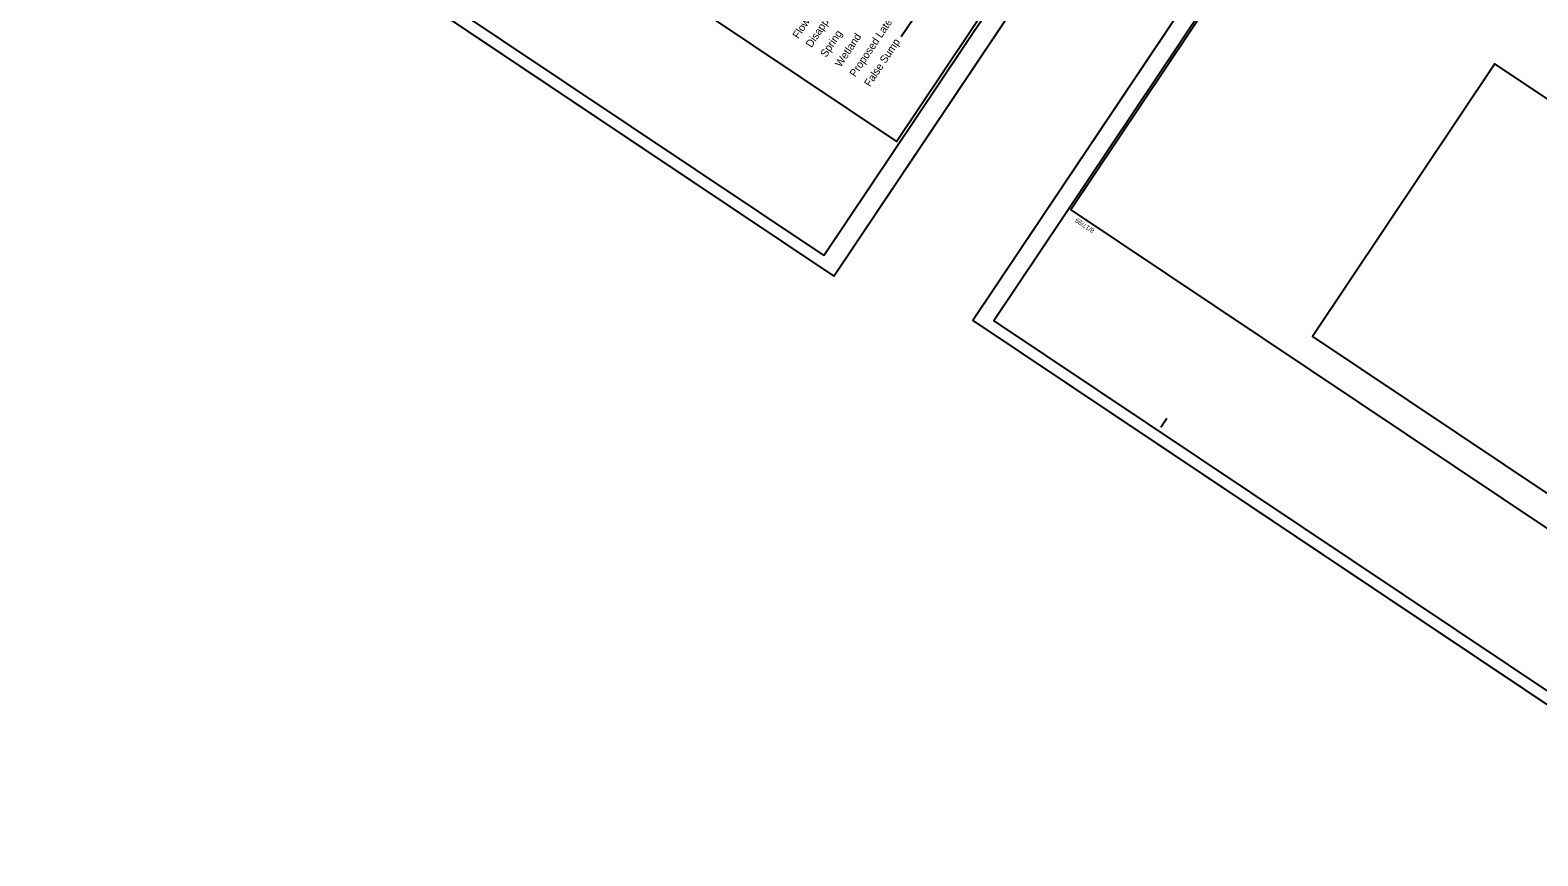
# Model space of a CAD drawing. Extents: x 1715610 to 1720914, y 798298 to 802505.
# Drawn here: x 1717996 to 1719710, y 798298 to 799237 of the extents above; entities that cross this region are included whole.
import ezdxf

# ---------------------------------------------------------------- set-up
doc = ezdxf.new("R2010")
doc.units = 0
for name, color, linetype in [('Default', 7, 'Continuous'), ('Sheet Cutting Line CELL', 7, 'Continuous'), ('Sheet Plan CELL', 7, 'Continuous'), ('Sheet Plot Border Inside CELL', 7, 'Continuous'), ('Sheet Plot Border Outside CELL', 7, 'Continuous'), ('Sheet Symbology CELL', 7, 'Continuous')]:
    doc.layers.add(name, color=color, linetype=linetype)

msp = doc.modelspace()

# ---------------------------------------------------------------- linework, layer by layer
at = {"layer": 'Default'}
msp.add_lwpolyline([(1719835.5, 798633.5), (1720043.1, 798943.6), (1719661.6, 799198.9), (1719454, 798888.8)], close=True, dxfattribs=at)
at = {"layer": 'Sheet Cutting Line CELL'}
for p, q in [((1718909.9, 798957.4), (1719846.5, 800356.9)), ((1720004.3, 800305.9), (1719067.9, 798906.9)), ((1717995.7, 799569.3), (1718909.9, 798957.4)), ((1719067.9, 798906.9), (1719977.9, 798297.8))]:
    msp.add_line(p, q, dxfattribs=at)
at = {"layer": 'Sheet Plan CELL'}
for p, q in [((1719179.2, 799032.7), (1719179.2, 799032.7)), ((1719281.5, 798785.6), (1719288.5, 798795.9))]:
    msp.add_line(p, q, dxfattribs=at)
msp.add_lwpolyline([(1720013.5, 800279.3), (1719179.2, 799032.7), (1720051.8, 798448.7), (1720886.1, 799695.2)], close=True, dxfattribs=at)
at = {"layer": 'Sheet Plot Border Inside CELL'}
for points in [[(1718898.4, 798980.7), (1719825.4, 800365.7), (1718948.6, 800952.5), (1718021.6, 799567.6)], [(1719968.5, 798319.7), (1720895.2, 799704.2), (1720018.4, 800291.1), (1719091.7, 798906.6)]]:
    msp.add_lwpolyline(points, close=True, dxfattribs=at)
at = {"layer": 'Sheet Plot Border Outside CELL'}
for points in [[(1718909.9, 798957.4), (1719846.5, 800356.9), (1718932.4, 800968.7), (1717995.7, 799569.3)], [(1719977.9, 798297.8), (1720914.3, 799696.9), (1720004.3, 800305.9), (1719067.9, 798906.9)]]:
    msp.add_lwpolyline(points, close=True, dxfattribs=at)
at = {"layer": 'Sheet Symbology CELL'}
msp.add_line((1719086.7, 799379.3), (1718986.4, 799229.5), dxfattribs=at)
msp.add_lwpolyline([(1718943.7, 800940.7), (1718109.4, 799694.2), (1718981.1, 799110.7), (1719815.5, 800357.2)], close=True, dxfattribs=at)

# ---------------------------------------------------------------- texts
at = {"layer": 'Sheet Plan CELL'}
msp.add_text('8/17/99', height=5.25, rotation=146.2051, dxfattribs=at).set_placement((1719206.6, 799010.4))
at = {"layer": 'Sheet Symbology CELL'}
for s, p in [('Proposed Lateral, Tail, Head Ditch', (1718934.2, 799183.3)), ('Disappearing Stream', (1718884.3, 799216.7)), ('Flow Arrow', (1718869.3, 799226.8)), ('Spring', (1718900.9, 799205.6)), ('Wetland', (1718917.6, 799194.4)), ('False Sump', (1718950.8, 799172.2))]:
    msp.add_text(s, height=8.75, rotation=56.2051, dxfattribs=at).set_placement(p)

doc.saveas('drawing.dxf')
